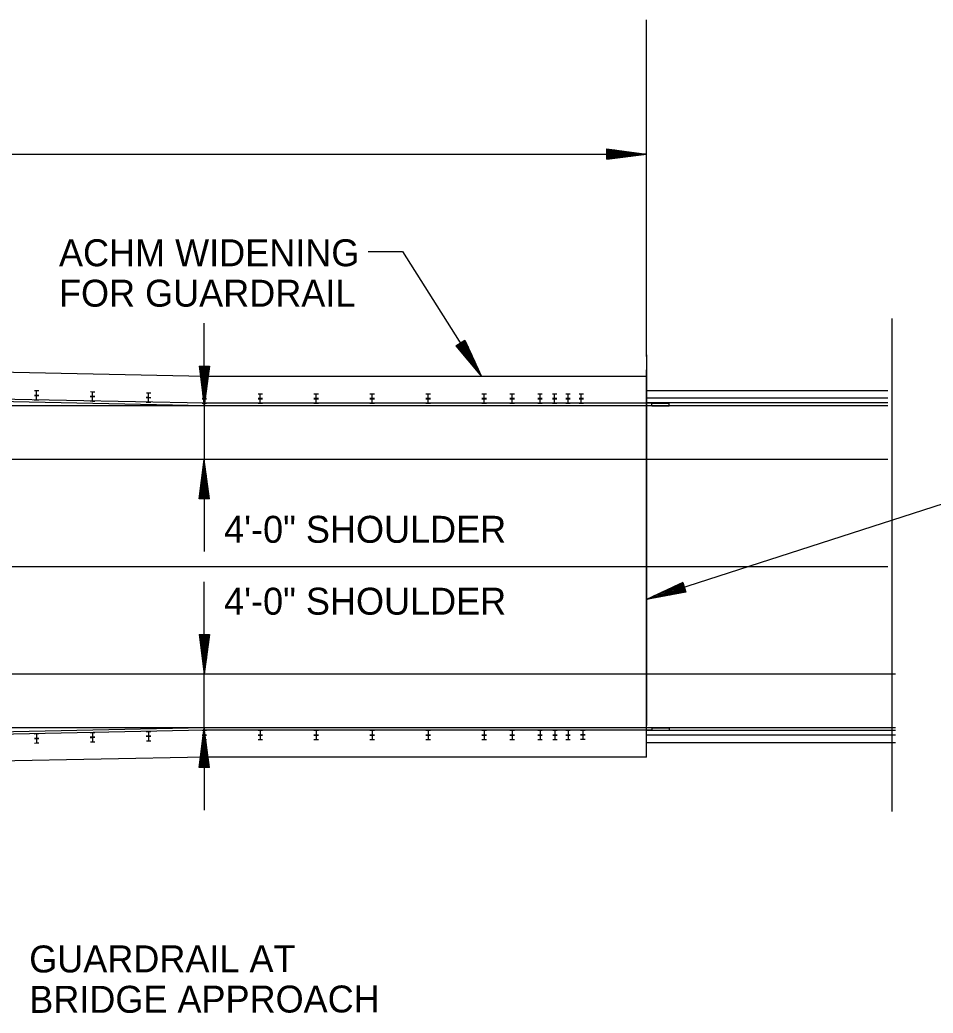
# Model space of a CAD drawing. Extents: x -2842 to 2681, y -2139 to 474.
# Drawn here: x -1856.1 to -1652.8, y -1736.2 to -1515.1 of the extents above; entities that cross this region are included whole.
import ezdxf

# ---------------------------------------------------------------- set-up
doc = ezdxf.new("R2010")
doc.units = 0
for name, color, linetype in [('Default', 7, 'Continuous'), ('R_Border', 7, 'Continuous'), ('R_Border Notes', 7, 'Continuous'), ('R_Grid', 7, 'Continuous')]:
    doc.layers.add(name, color=color, linetype=linetype)

msp = doc.modelspace()

# ---------------------------------------------------------------- linework, layer by layer
at = {"layer": 'Default'}
for p, q in [((-1716.57, -1589.99), (-1716.57, -1515.05)), ((-1662.01, -1581.52), (-1662.01, -1691.33)), ((-1814.89, -1594.45), (-2263.31, -1585.48)), ((-1716.57, -1589.67), (-1716.57, -1672.22)), ((-1815.02, -1600.97), (-2263.45, -1592)), ((-1815, -1600.43), (-2263.43, -1591.46)), ((-1716.57, -1590.47), (-1716.57, -1597.64)), ((-1716.57, -1594.45), (-1815.02, -1594.45)), ((-1716.57, -1676.03), (-1716.57, -1593)), ((-1852.85, -1598.6), (-1852.36, -1598.6)), ((-1852.85, -1598.68), (-1852.36, -1598.68)), ((-1852.83, -1597.6), (-1852.34, -1597.6)), ((-1852.38, -1599.67), (-1852.36, -1598.68)), ((-1852.36, -1598.6), (-1852.34, -1597.6)), ((-1852.36, -1598.6), (-1851.86, -1598.62)), ((-1852.36, -1598.68), (-1851.86, -1598.7)), ((-1852.34, -1597.6), (-1851.84, -1597.62)), ((-1840.4, -1598.84), (-1839.9, -1598.86)), ((-1840.4, -1598.92), (-1839.9, -1598.94)), ((-1840.38, -1597.84), (-1839.88, -1597.86)), ((-1839.92, -1599.93), (-1839.9, -1598.94)), ((-1839.9, -1598.86), (-1839.88, -1597.86)), ((-1839.9, -1598.86), (-1839.4, -1598.86)), ((-1839.9, -1598.94), (-1839.4, -1598.94)), ((-1839.88, -1597.86), (-1839.38, -1597.86)), ((-1827.94, -1599.1), (-1827.44, -1599.1)), ((-1827.94, -1599.18), (-1827.44, -1599.18)), ((-1827.92, -1598.1), (-1827.42, -1598.1)), ((-1827.46, -1600.17), (-1827.44, -1599.18)), ((-1827.44, -1599.1), (-1827.42, -1598.1)), ((-1827.44, -1599.1), (-1826.94, -1599.12)), ((-1827.44, -1599.18), (-1826.94, -1599.2)), ((-1827.42, -1598.1), (-1826.92, -1598.12)), ((-1815.52, -1598.34), (-1815.02, -1598.34)), ((-1815.02, -1599.33), (-1815.02, -1598.34)), ((-1815.02, -1598.34), (-1814.53, -1598.34)), ((-1803.07, -1598.34), (-1802.57, -1598.34)), ((-1802.57, -1599.33), (-1802.57, -1598.34)), ((-1802.57, -1598.34), (-1802.07, -1598.34)), ((-1790.61, -1598.34), (-1790.11, -1598.34)), ((-1790.11, -1599.33), (-1790.11, -1598.34)), ((-1790.11, -1598.34), (-1789.61, -1598.34)), ((-1778.15, -1598.34), (-1777.65, -1598.34)), ((-1777.65, -1599.33), (-1777.65, -1598.34)), ((-1777.65, -1598.34), (-1777.16, -1598.34)), ((-1765.7, -1598.34), (-1765.2, -1598.34)), ((-1765.2, -1599.33), (-1765.2, -1598.34)), ((-1765.2, -1598.34), (-1764.7, -1598.34)), ((-1753.24, -1598.34), (-1752.74, -1598.34)), ((-1752.74, -1599.33), (-1752.74, -1598.34)), ((-1752.74, -1598.34), (-1752.24, -1598.34)), ((-1747, -1598.34), (-1746.5, -1598.34)), ((-1746.5, -1599.33), (-1746.5, -1598.34)), ((-1746.5, -1598.34), (-1746, -1598.34)), ((-1740.78, -1598.34), (-1740.28, -1598.34)), ((-1740.28, -1599.33), (-1740.28, -1598.34)), ((-1740.28, -1598.34), (-1739.79, -1598.34)), ((-1737.53, -1598.34), (-1737.04, -1598.34)), ((-1737.04, -1599.33), (-1737.04, -1598.34)), ((-1737.04, -1598.34), (-1736.54, -1598.34)), ((-1734.54, -1598.34), (-1734.05, -1598.34)), ((-1734.05, -1599.33), (-1734.05, -1598.34)), ((-1734.05, -1598.34), (-1733.55, -1598.34)), ((-1731.59, -1598.34), (-1731.1, -1598.34)), ((-1731.1, -1599.33), (-1731.1, -1598.34)), ((-1731.1, -1598.34), (-1730.6, -1598.34)), ((-1662.85, -1597.64), (-1716.57, -1597.64)), ((-1815.02, -1600.97), (-2381.26, -1600.97)), ((-1852.87, -1599.67), (-1852.38, -1599.67)), ((-1852.38, -1599.67), (-1851.88, -1599.69)), ((-1840.42, -1599.91), (-1839.92, -1599.93)), ((-1839.92, -1599.93), (-1839.42, -1599.93)), ((-1827.96, -1600.17), (-1827.46, -1600.17)), ((-1827.46, -1600.17), (-1826.96, -1600.19)), ((-1815.52, -1599.33), (-1815.02, -1599.33)), ((-1815.52, -1599.43), (-1815.02, -1599.43)), ((-1815.52, -1600.43), (-1815.02, -1600.43)), ((-1815.02, -1599.33), (-1814.53, -1599.33)), ((-1815.02, -1600.43), (-1815.02, -1599.43)), ((-1815.02, -1599.43), (-1814.53, -1599.43)), ((-1715.37, -1600.43), (-1815.02, -1600.43)), ((-1815.02, -1600.43), (-1814.53, -1600.43)), ((-1715.37, -1600.97), (-1815.02, -1600.97)), ((-1714.77, -1600.97), (-1813.23, -1600.97)), ((-1803.07, -1599.33), (-1802.57, -1599.33)), ((-1803.07, -1599.43), (-1802.57, -1599.43)), ((-1803.07, -1600.43), (-1802.57, -1600.43)), ((-1802.57, -1599.33), (-1802.07, -1599.33)), ((-1802.57, -1600.43), (-1802.57, -1599.43)), ((-1802.57, -1599.43), (-1802.07, -1599.43)), ((-1802.57, -1600.43), (-1802.07, -1600.43)), ((-1790.61, -1599.33), (-1790.11, -1599.33)), ((-1790.61, -1599.43), (-1790.11, -1599.43)), ((-1790.61, -1600.43), (-1790.11, -1600.43)), ((-1790.11, -1599.33), (-1789.61, -1599.33)), ((-1790.11, -1600.43), (-1790.11, -1599.43)), ((-1790.11, -1599.43), (-1789.61, -1599.43)), ((-1790.11, -1600.43), (-1789.61, -1600.43)), ((-1778.15, -1599.33), (-1777.65, -1599.33)), ((-1778.15, -1599.43), (-1777.65, -1599.43)), ((-1778.15, -1600.43), (-1777.65, -1600.43)), ((-1777.65, -1599.33), (-1777.16, -1599.33)), ((-1777.65, -1600.43), (-1777.65, -1599.43)), ((-1777.65, -1599.43), (-1777.16, -1599.43)), ((-1777.65, -1600.43), (-1777.16, -1600.43)), ((-1765.7, -1599.33), (-1765.2, -1599.33)), ((-1765.7, -1599.43), (-1765.2, -1599.43)), ((-1765.7, -1600.43), (-1765.2, -1600.43)), ((-1765.2, -1599.33), (-1764.7, -1599.33)), ((-1765.2, -1600.43), (-1765.2, -1599.43)), ((-1765.2, -1599.43), (-1764.7, -1599.43)), ((-1765.2, -1600.43), (-1764.7, -1600.43)), ((-1753.24, -1599.33), (-1752.74, -1599.33)), ((-1753.24, -1599.43), (-1752.74, -1599.43)), ((-1753.24, -1600.43), (-1752.74, -1600.43)), ((-1752.74, -1599.33), (-1752.24, -1599.33)), ((-1752.74, -1600.43), (-1752.74, -1599.43)), ((-1752.74, -1599.43), (-1752.24, -1599.43)), ((-1752.74, -1600.43), (-1752.24, -1600.43)), ((-1747, -1599.33), (-1746.5, -1599.33)), ((-1747, -1599.43), (-1746.5, -1599.43)), ((-1747, -1600.43), (-1746.5, -1600.43)), ((-1746.5, -1599.33), (-1746, -1599.33)), ((-1746.5, -1600.43), (-1746.5, -1599.43)), ((-1746.5, -1599.43), (-1746, -1599.43)), ((-1746.5, -1600.43), (-1746, -1600.43)), ((-1740.78, -1599.33), (-1740.28, -1599.33)), ((-1740.78, -1599.43), (-1740.28, -1599.43)), ((-1740.78, -1600.43), (-1740.28, -1600.43)), ((-1740.28, -1599.33), (-1739.79, -1599.33)), ((-1740.28, -1600.43), (-1740.28, -1599.43)), ((-1740.28, -1599.43), (-1739.79, -1599.43)), ((-1740.28, -1600.43), (-1739.79, -1600.43)), ((-1737.53, -1599.33), (-1737.04, -1599.33)), ((-1737.53, -1599.43), (-1737.04, -1599.43)), ((-1737.53, -1600.43), (-1737.04, -1600.43)), ((-1737.04, -1599.33), (-1736.54, -1599.33)), ((-1737.04, -1600.43), (-1737.04, -1599.43)), ((-1737.04, -1599.43), (-1736.54, -1599.43)), ((-1737.04, -1600.43), (-1736.54, -1600.43)), ((-1734.54, -1599.33), (-1734.05, -1599.33)), ((-1734.54, -1599.43), (-1734.05, -1599.43)), ((-1734.54, -1600.43), (-1734.05, -1600.43)), ((-1734.05, -1599.33), (-1733.55, -1599.33)), ((-1734.05, -1600.43), (-1734.05, -1599.43)), ((-1734.05, -1599.43), (-1733.55, -1599.43)), ((-1734.05, -1600.43), (-1733.55, -1600.43)), ((-1731.59, -1599.33), (-1731.1, -1599.33)), ((-1731.59, -1599.43), (-1731.1, -1599.43)), ((-1731.59, -1600.43), (-1731.1, -1600.43)), ((-1731.1, -1599.33), (-1730.6, -1599.33)), ((-1731.1, -1600.43), (-1731.1, -1599.43)), ((-1731.1, -1599.43), (-1730.6, -1599.43)), ((-1731.1, -1600.43), (-1730.6, -1600.43)), ((-1662.85, -1599.3), (-1716.57, -1599.3)), ((-1662.85, -1600.33), (-1716.57, -1600.33)), ((-1662.85, -1600.97), (-1716.57, -1600.97)), ((-1715.37, -1600.97), (-1715.37, -1600.43)), ((-1715.37, -1600.43), (-1711.58, -1600.43)), ((-1715.37, -1600.97), (-1711.58, -1600.97)), ((-1711.58, -1600.97), (-1711.58, -1600.43)), ((-1662.85, -1612.93), (-2773.74, -1612.93)), ((-1661.2, -1660.76), (-2773.74, -1660.76)), ((-1815.02, -1672.72), (-2773.74, -1672.72)), ((-1815.02, -1672.72), (-2163.82, -1679.7)), ((-1815, -1673.26), (-2163.8, -1680.23)), ((-1852.87, -1674.02), (-1852.38, -1674)), ((-1852.38, -1674), (-1851.88, -1674)), ((-1852.38, -1674), (-1852.36, -1674.99)), ((-1840.42, -1673.76), (-1839.92, -1673.76)), ((-1839.92, -1673.76), (-1839.42, -1673.74)), ((-1839.92, -1673.76), (-1839.9, -1674.75)), ((-1827.96, -1673.52), (-1827.46, -1673.5)), ((-1827.46, -1673.5), (-1826.96, -1673.5)), ((-1827.46, -1673.5), (-1827.44, -1674.49)), ((-1815.52, -1673.26), (-1815.02, -1673.26)), ((-1815.52, -1674.26), (-1815.02, -1674.26)), ((-1815.52, -1674.33), (-1815.02, -1674.33)), ((-1715.37, -1672.72), (-1815.02, -1672.72)), ((-1715.37, -1673.26), (-1815.02, -1673.26)), ((-1815.02, -1673.26), (-1814.53, -1673.26)), ((-1815.02, -1673.26), (-1815.02, -1674.26)), ((-1815.02, -1674.26), (-1814.53, -1674.26)), ((-1815.02, -1674.33), (-1814.53, -1674.33)), ((-1815.02, -1674.33), (-1815.02, -1675.33)), ((-1803.07, -1673.26), (-1802.57, -1673.26)), ((-1803.07, -1674.26), (-1802.57, -1674.26)), ((-1803.07, -1674.33), (-1802.57, -1674.33)), ((-1802.57, -1673.26), (-1802.07, -1673.26)), ((-1802.57, -1673.26), (-1802.57, -1674.26)), ((-1802.57, -1674.26), (-1802.07, -1674.26)), ((-1802.57, -1674.33), (-1802.07, -1674.33)), ((-1802.57, -1674.33), (-1802.57, -1675.33)), ((-1790.61, -1673.26), (-1790.11, -1673.26)), ((-1790.61, -1674.26), (-1790.11, -1674.26)), ((-1790.61, -1674.33), (-1790.11, -1674.33)), ((-1790.11, -1673.26), (-1789.61, -1673.26)), ((-1790.11, -1673.26), (-1790.11, -1674.26)), ((-1790.11, -1674.26), (-1789.61, -1674.26)), ((-1790.11, -1674.33), (-1789.61, -1674.33)), ((-1790.11, -1674.33), (-1790.11, -1675.33)), ((-1778.15, -1673.26), (-1777.65, -1673.26)), ((-1778.15, -1674.26), (-1777.65, -1674.26)), ((-1778.15, -1674.33), (-1777.65, -1674.33)), ((-1777.65, -1673.26), (-1777.16, -1673.26)), ((-1777.65, -1673.26), (-1777.65, -1674.26)), ((-1777.65, -1674.26), (-1777.16, -1674.26)), ((-1777.65, -1674.33), (-1777.16, -1674.33)), ((-1777.65, -1674.33), (-1777.65, -1675.33)), ((-1765.7, -1673.26), (-1765.2, -1673.26)), ((-1765.7, -1674.26), (-1765.2, -1674.26)), ((-1765.7, -1674.33), (-1765.2, -1674.33)), ((-1765.2, -1673.26), (-1764.7, -1673.26)), ((-1765.2, -1673.26), (-1765.2, -1674.26)), ((-1765.2, -1674.26), (-1764.7, -1674.26)), ((-1765.2, -1674.33), (-1764.7, -1674.33)), ((-1765.2, -1674.33), (-1765.2, -1675.33)), ((-1753.24, -1673.26), (-1752.74, -1673.26)), ((-1753.24, -1674.26), (-1752.74, -1674.26)), ((-1753.24, -1674.33), (-1752.74, -1674.33)), ((-1752.74, -1673.26), (-1752.24, -1673.26)), ((-1752.74, -1673.26), (-1752.74, -1674.26)), ((-1752.74, -1674.26), (-1752.24, -1674.26)), ((-1752.74, -1674.33), (-1752.24, -1674.33)), ((-1752.74, -1674.33), (-1752.74, -1675.33)), ((-1747, -1673.26), (-1746.5, -1673.26)), ((-1747, -1674.26), (-1746.5, -1674.26)), ((-1747, -1674.33), (-1746.5, -1674.33)), ((-1746.5, -1673.26), (-1746, -1673.26)), ((-1746.5, -1673.26), (-1746.5, -1674.26)), ((-1746.5, -1674.26), (-1746, -1674.26)), ((-1746.5, -1674.33), (-1746, -1674.33)), ((-1746.5, -1674.33), (-1746.5, -1675.33)), ((-1740.78, -1673.26), (-1740.28, -1673.26)), ((-1740.78, -1674.26), (-1740.28, -1674.26)), ((-1740.78, -1674.33), (-1740.28, -1674.33)), ((-1740.28, -1673.26), (-1739.79, -1673.26)), ((-1740.28, -1673.26), (-1740.28, -1674.26)), ((-1740.28, -1674.26), (-1739.79, -1674.26)), ((-1740.28, -1674.33), (-1739.79, -1674.33)), ((-1740.28, -1674.33), (-1740.28, -1675.33)), ((-1737.47, -1673.26), (-1736.98, -1673.26)), ((-1737.47, -1674.26), (-1736.98, -1674.26)), ((-1737.47, -1674.33), (-1736.98, -1674.33)), ((-1736.98, -1673.26), (-1736.48, -1673.26)), ((-1736.98, -1673.26), (-1736.98, -1674.26)), ((-1736.98, -1674.26), (-1736.48, -1674.26)), ((-1736.98, -1674.33), (-1736.48, -1674.33)), ((-1736.98, -1674.33), (-1736.98, -1675.33)), ((-1734.54, -1673.26), (-1734.05, -1673.26)), ((-1734.54, -1674.26), (-1734.05, -1674.26)), ((-1734.54, -1674.33), (-1734.05, -1674.33)), ((-1734.05, -1673.26), (-1733.55, -1673.26)), ((-1734.05, -1673.26), (-1734.05, -1674.26)), ((-1734.05, -1674.26), (-1733.55, -1674.26)), ((-1734.05, -1674.33), (-1733.55, -1674.33)), ((-1734.05, -1674.33), (-1734.05, -1675.33)), ((-1731.26, -1673.2), (-1730.76, -1673.2)), ((-1731.26, -1674.2), (-1730.76, -1674.2)), ((-1731.26, -1674.28), (-1730.76, -1674.28)), ((-1730.76, -1673.2), (-1730.26, -1673.2)), ((-1730.76, -1673.2), (-1730.76, -1674.2)), ((-1730.76, -1674.2), (-1730.26, -1674.2)), ((-1730.76, -1674.28), (-1730.26, -1674.28)), ((-1730.76, -1674.28), (-1730.76, -1675.27)), ((-1661.2, -1672.72), (-1716.57, -1672.72)), ((-1661.2, -1673.34), (-1716.57, -1673.34)), ((-1661.2, -1674.37), (-1716.57, -1674.37)), ((-1715.37, -1672.72), (-1715.37, -1673.26)), ((-1715.37, -1672.72), (-1711.58, -1672.72)), ((-1715.37, -1673.26), (-1711.58, -1673.26)), ((-1711.58, -1672.72), (-1711.58, -1673.26)), ((-1852.85, -1675.01), (-1852.36, -1674.99)), ((-1852.85, -1675.09), (-1852.36, -1675.07)), ((-1852.83, -1676.09), (-1852.34, -1676.07)), ((-1852.36, -1674.99), (-1851.86, -1674.99)), ((-1852.36, -1675.07), (-1851.86, -1675.07)), ((-1852.36, -1675.07), (-1852.34, -1676.07)), ((-1852.34, -1676.07), (-1851.84, -1676.07)), ((-1840.4, -1674.75), (-1839.9, -1674.75)), ((-1840.4, -1674.83), (-1839.9, -1674.83)), ((-1840.38, -1675.83), (-1839.88, -1675.83)), ((-1839.9, -1674.75), (-1839.4, -1674.73)), ((-1839.9, -1674.83), (-1839.4, -1674.81)), ((-1839.9, -1674.83), (-1839.88, -1675.83)), ((-1839.88, -1675.83), (-1839.38, -1675.81)), ((-1827.94, -1674.51), (-1827.44, -1674.49)), ((-1827.94, -1674.59), (-1827.44, -1674.57)), ((-1827.92, -1675.59), (-1827.42, -1675.57)), ((-1827.44, -1674.49), (-1826.94, -1674.49)), ((-1827.44, -1674.57), (-1826.94, -1674.57)), ((-1827.44, -1674.57), (-1827.42, -1675.57)), ((-1827.42, -1675.57), (-1826.92, -1675.57)), ((-1815.52, -1675.33), (-1815.02, -1675.33)), ((-1815.02, -1675.33), (-1814.53, -1675.33)), ((-1803.07, -1675.33), (-1802.57, -1675.33)), ((-1802.57, -1675.33), (-1802.07, -1675.33)), ((-1790.61, -1675.33), (-1790.11, -1675.33)), ((-1790.11, -1675.33), (-1789.61, -1675.33)), ((-1778.15, -1675.33), (-1777.65, -1675.33)), ((-1777.65, -1675.33), (-1777.16, -1675.33)), ((-1765.7, -1675.33), (-1765.2, -1675.33)), ((-1765.2, -1675.33), (-1764.7, -1675.33)), ((-1753.24, -1675.33), (-1752.74, -1675.33)), ((-1752.74, -1675.33), (-1752.24, -1675.33)), ((-1747, -1675.33), (-1746.5, -1675.33)), ((-1746.5, -1675.33), (-1746, -1675.33)), ((-1740.78, -1675.33), (-1740.28, -1675.33)), ((-1740.28, -1675.33), (-1739.79, -1675.33)), ((-1737.47, -1675.33), (-1736.98, -1675.33)), ((-1736.98, -1675.33), (-1736.48, -1675.33)), ((-1734.54, -1675.33), (-1734.05, -1675.33)), ((-1734.05, -1675.33), (-1733.55, -1675.33)), ((-1731.26, -1675.27), (-1730.76, -1675.27)), ((-1730.76, -1675.27), (-1730.26, -1675.27)), ((-1661.2, -1676.03), (-1716.57, -1676.03)), ((-1716.57, -1679.24), (-1716.57, -1676.03)), ((-1814.89, -1679.24), (-2163.68, -1686.21)), ((-1716.57, -1679.24), (-1815.02, -1679.24))]:
    msp.add_line(p, q, dxfattribs=at)
at = {"layer": 'R_Border Notes'}
for p, q in [((-1725.39, -1543.81), (-1716.57, -1544.95)), ((-1725.39, -1546.1), (-1725.39, -1543.81)), ((-2363.24, -1544.95), (-1716.57, -1544.95)), ((-1725.4, -1544.49), (-1720.09, -1544.5)), ((-1725.39, -1544.03), (-1723.66, -1544.03)), ((-1725.39, -1544.27), (-1721.87, -1544.26)), ((-1725.39, -1544.73), (-1718.36, -1544.73)), ((-1716.57, -1544.95), (-1725.39, -1544.95)), ((-1725.39, -1546.1), (-1716.57, -1544.95)), ((-1725.39, -1545.18), (-1718.36, -1545.18)), ((-1725.39, -1545.41), (-1720.09, -1545.4)), ((-1725.39, -1545.87), (-1723.65, -1545.86)), ((-1725.38, -1545.64), (-1721.87, -1545.64)), ((-1815.02, -1600.97), (-1815.02, -1582.62)), ((-1759, -1587.61), (-1757.06, -1586.39)), ((-1759, -1587.61), (-1753.31, -1594.45)), ((-1758.8, -1587.49), (-1757.87, -1588.95)), ((-1758.61, -1587.37), (-1756.72, -1590.34)), ((-1758.42, -1587.24), (-1755.57, -1591.72)), ((-1758.22, -1587.12), (-1754.46, -1593.06)), ((-1753.31, -1594.45), (-1758.03, -1587)), ((-1757.84, -1586.88), (-1754.08, -1592.82)), ((-1757.64, -1586.75), (-1754.81, -1591.23)), ((-1757.45, -1586.63), (-1755.56, -1589.6)), ((-1757.25, -1586.5), (-1756.32, -1587.97)), ((-1757.06, -1586.39), (-1753.31, -1594.45)), ((-1816.17, -1592.15), (-1813.88, -1592.14)), ((-1816.17, -1592.15), (-1815.02, -1600.97)), ((-1815.95, -1592.15), (-1815.94, -1593.88)), ((-1815.72, -1592.15), (-1815.71, -1595.67)), ((-1815.48, -1592.14), (-1815.48, -1597.45)), ((-1815.25, -1592.15), (-1815.25, -1599.18)), ((-1813.88, -1592.14), (-1815.02, -1600.97)), ((-1815.02, -1600.97), (-1815.02, -1592.15)), ((-1814.8, -1592.14), (-1814.8, -1599.18)), ((-1814.57, -1592.14), (-1814.57, -1597.45)), ((-1814.34, -1592.14), (-1814.34, -1595.66)), ((-1814.11, -1592.14), (-1814.11, -1593.88)), ((-1815.02, -1600.97), (-1815.02, -1612.93)), ((-1816.17, -1621.75), (-1815.02, -1612.93)), ((-1815.02, -1612.93), (-1815.02, -1633.46)), ((-1815.02, -1612.93), (-1815.02, -1621.75)), ((-1813.88, -1621.75), (-1815.02, -1612.93)), ((-1815.48, -1621.76), (-1815.48, -1616.45)), ((-1815.24, -1621.75), (-1815.25, -1614.72)), ((-1814.8, -1621.75), (-1814.8, -1614.72)), ((-1814.57, -1621.75), (-1814.57, -1616.45)), ((-1815.71, -1621.76), (-1815.71, -1618.23)), ((-1814.33, -1621.75), (-1814.34, -1618.23)), ((-1815.94, -1621.75), (-1815.94, -1620.02)), ((-1814.1, -1621.75), (-1814.11, -1620.02)), ((-1813.88, -1621.75), (-1816.17, -1621.75)), ((-1815.02, -1660.76), (-1815.02, -1640.23)), ((-1708.52, -1640.32), (-1716.57, -1644.12)), ((-1708.24, -1641.19), (-1714.93, -1643.35)), ((-1708.31, -1640.97), (-1713.35, -1642.61)), ((-1708.39, -1640.75), (-1711.73, -1641.84)), ((-1708.45, -1640.53), (-1710.1, -1641.07)), ((-1708.52, -1640.32), (-1707.82, -1642.49)), ((-1716.57, -1644.12), (-1708.17, -1641.41)), ((-1707.82, -1642.49), (-1716.57, -1644.12)), ((-1708.1, -1641.62), (-1714.79, -1643.78)), ((-1708.02, -1641.84), (-1713.07, -1643.47)), ((-1707.96, -1642.06), (-1711.3, -1643.14)), ((-1707.89, -1642.28), (-1709.53, -1642.81)), ((-1816.17, -1651.94), (-1815.02, -1660.76)), ((-1816.17, -1651.94), (-1813.88, -1651.94)), ((-1815.95, -1651.94), (-1815.94, -1653.67)), ((-1815.72, -1651.94), (-1815.71, -1655.46)), ((-1815.48, -1651.94), (-1815.48, -1657.24)), ((-1815.25, -1651.94), (-1815.25, -1658.97)), ((-1815.02, -1660.76), (-1815.02, -1651.94)), ((-1813.88, -1651.94), (-1815.02, -1660.76)), ((-1814.8, -1651.94), (-1814.8, -1658.97)), ((-1814.57, -1651.93), (-1814.57, -1657.24)), ((-1814.34, -1651.93), (-1814.34, -1655.46)), ((-1814.11, -1651.94), (-1814.11, -1653.67)), ((-1815.02, -1672.72), (-1815.02, -1660.76)), ((-1816.17, -1681.55), (-1815.02, -1672.72)), ((-1815.02, -1672.72), (-1815.02, -1691.07)), ((-1815.02, -1672.72), (-1815.02, -1681.54)), ((-1813.88, -1681.54), (-1815.02, -1672.72)), ((-1815.48, -1681.55), (-1815.48, -1676.24)), ((-1815.24, -1681.55), (-1815.25, -1674.51)), ((-1814.8, -1681.54), (-1814.8, -1674.51)), ((-1814.57, -1681.55), (-1814.57, -1676.24)), ((-1815.71, -1681.55), (-1815.71, -1678.03)), ((-1814.33, -1681.54), (-1814.34, -1678.02)), ((-1815.94, -1681.55), (-1815.94, -1679.81)), ((-1814.1, -1681.54), (-1814.11, -1679.81)), ((-1813.88, -1681.54), (-1816.17, -1681.55))]:
    msp.add_line(p, q, dxfattribs=at)
for points in [[(-1778.55, -1566.6), (-1770.94, -1566.6), (-1753.31, -1594.45)], [(-1626.73, -1618.37), (-1636.79, -1618.37), (-1716.57, -1644.12)]]:
    msp.add_lwpolyline(points, dxfattribs=at)
at = {"layer": 'R_Grid'}
msp.add_line((-1662.85, -1636.84), (-2773.74, -1636.84), dxfattribs=at)

# ---------------------------------------------------------------- texts
at = {"layer": 'R_Border'}
for s, p in [('ACHM WIDENING', (-1847.37, -1569.92)), ('FOR GUARDRAIL', (-1847.37, -1578.92)), ('4\'-0" SHOULDER', (-1810.61, -1631.5)), ('4\'-0" SHOULDER', (-1810.61, -1647.51))]:
    msp.add_text(s, height=6, dxfattribs=at).set_placement(p)
for s, p in [('GUARDRAIL AT', (-1854, -1727.19)), ('BRIDGE APPROACH ', (-1853.99, -1736.19))]:
    msp.add_text(s, height=6, rotation=0.0775, dxfattribs=at).set_placement(p)

doc.saveas('drawing.dxf')
